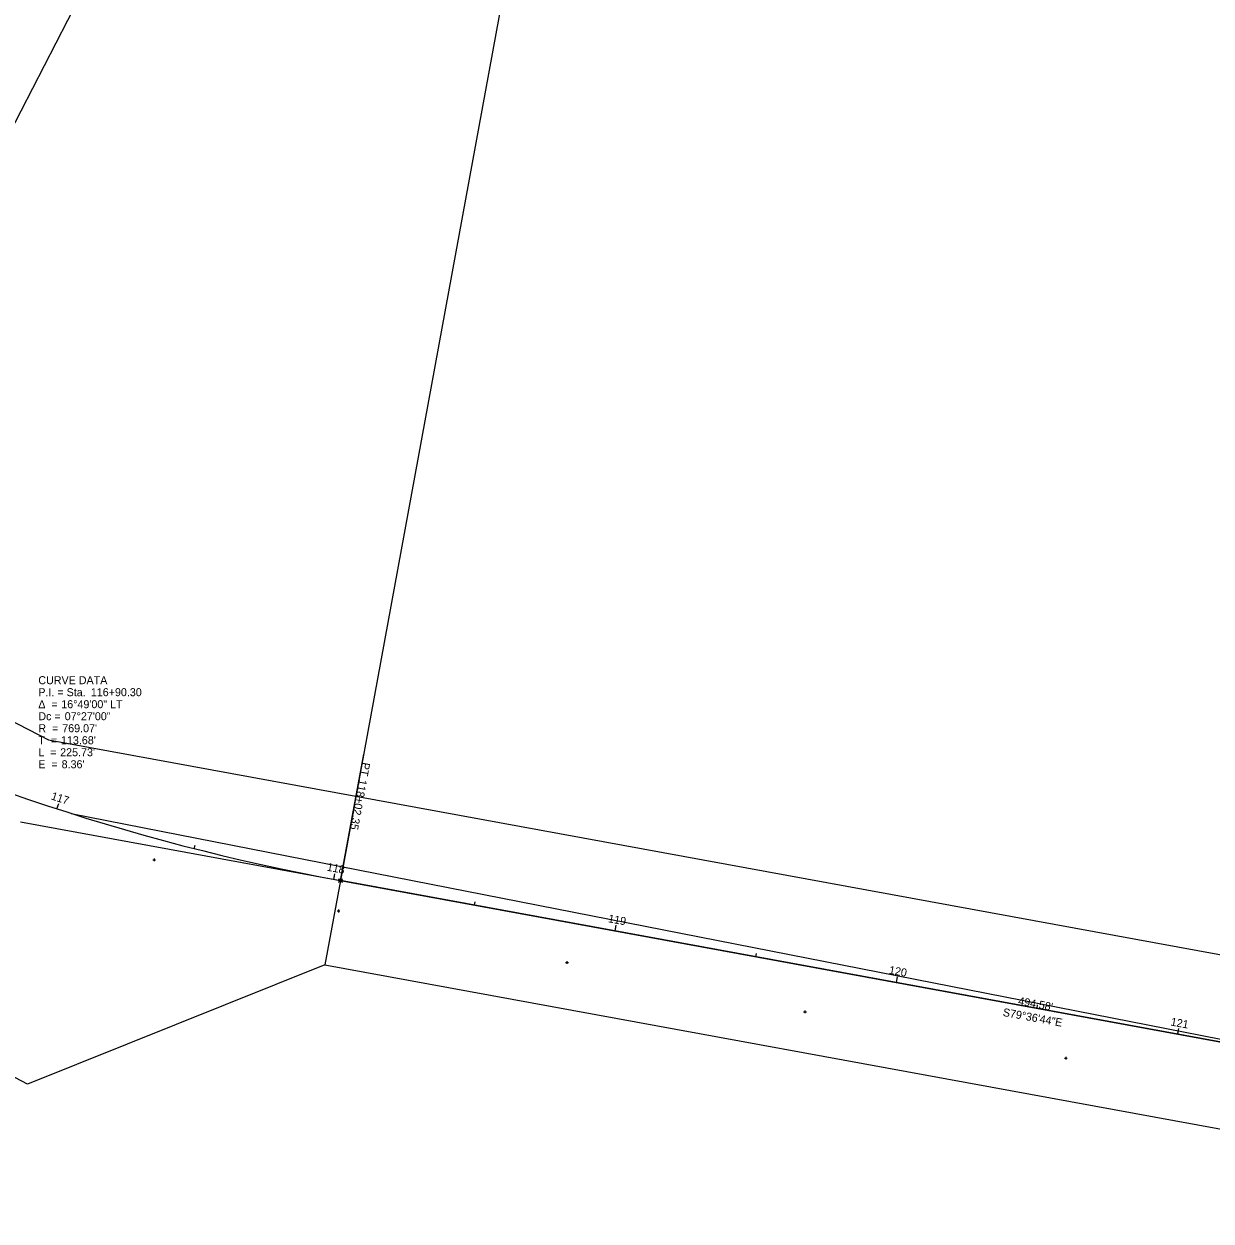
# Model space of a CAD drawing. Extents: x 2003596 to 2006888, y 571866 to 574416.
# Drawn here: x 2004434.3 to 2004849.5, y 572605.4 to 573024.1 of the extents above; entities that cross this region are included whole.
import ezdxf

# ---------------------------------------------------------------- set-up
doc = ezdxf.new("R2010")
doc.units = 0
for name, color, linetype in [('GE_X_Alignment', 7, 'Continuous'), ('GE_X_Alignment_1000_Bearings', 7, 'Continuous'), ('GE_X_Alignment_1000_Cardinal_Points', 7, 'Continuous'), ('GE_X_Alignment_1000_Curve_Data', 7, 'Continuous'), ('GE_X_Alignment_1000_Distances', 7, 'Continuous'), ('GE_X_Alignment_1000_Stations', 7, 'Continuous'), ('GE_X_Alignment_100_Bearings', 7, 'Continuous'), ('GE_X_Alignment_100_Cardinal_Points', 7, 'Continuous'), ('GE_X_Alignment_100_Distances', 7, 'Continuous'), ('GE_X_Alignment_100_Stations', 7, 'Continuous'), ('GE_X_Alignment_500_Bearings', 7, 'Continuous'), ('GE_X_Alignment_500_Cardinal_Points', 7, 'Continuous'), ('GE_X_Alignment_500_Distances', 7, 'Continuous'), ('GE_X_Alignment_500_Stations', 7, 'Continuous'), ('RW_X_CL', 7, 'Continuous'), ('RW_X_Esmt_SH', 7, 'Continuous'), ('SC_Scratch1', 7, 'Continuous'), ('SC_Scratch8', 7, 'Continuous'), ('SV_X_Random_Point', 7, 'Continuous'), ('SV_X_Shot_Marker', 7, 'Continuous')]:
    doc.layers.add(name, color=color, linetype=linetype)

msp = doc.modelspace()

# ---------------------------------------------------------------- linework, layer by layer
at = {"layer": 'GE_X_Alignment'}
msp.add_line((2004545, 572724.5), (2005031.48, 572635.32), dxfattribs=at)
msp.add_arc((2004683.7, 573480.96), 769.07, 242.79359, 259.61026, dxfattribs=at)
at = {"layer": 'GE_X_Alignment_1000_Cardinal_Points'}
msp.add_line((2004545, 572724.5), (2004553.12, 572768.76), dxfattribs=at)
msp.add_circle((2004545, 572724.5), 0.6, dxfattribs=at)
at = {"layer": 'GE_X_Alignment_1000_Stations'}
msp.add_line((2004739.42, 572688.86), (2004739.78, 572690.83), dxfattribs=at)
at = {"layer": 'GE_X_Alignment_100_Cardinal_Points'}
msp.add_line((2004545, 572724.5), (2004553.12, 572768.76), dxfattribs=at)
msp.add_circle((2004545, 572724.5), 0.6, dxfattribs=at)
at = {"layer": 'GE_X_Alignment_100_Stations'}
for p, q in [((2004445.86, 572749.59), (2004446.48, 572751.49)), ((2004493.88, 572735.68), (2004494.17, 572736.85)), ((2004542.7, 572724.92), (2004543.06, 572726.89)), ((2004591.88, 572715.91), (2004592.09, 572717.09)), ((2004641.06, 572706.89), (2004641.42, 572708.86)), ((2004690.24, 572697.87), (2004690.45, 572699.05)), ((2004739.42, 572688.86), (2004739.78, 572690.83)), ((2004788.6, 572679.84), (2004788.81, 572681.02)), ((2004837.78, 572670.83), (2004838.14, 572672.79))]:
    msp.add_line(p, q, dxfattribs=at)
at = {"layer": 'GE_X_Alignment_500_Cardinal_Points'}
msp.add_line((2004545, 572724.5), (2004553.12, 572768.76), dxfattribs=at)
msp.add_circle((2004545, 572724.5), 0.6, dxfattribs=at)
at = {"layer": 'GE_X_Alignment_500_Stations'}
for p, q in [((2004445.86, 572749.59), (2004446.23, 572750.73)), ((2004542.7, 572724.92), (2004542.92, 572726.1)), ((2004641.06, 572706.89), (2004641.27, 572708.07)), ((2004739.42, 572688.86), (2004739.78, 572690.83)), ((2004837.78, 572670.83), (2004837.99, 572672.01))]:
    msp.add_line(p, q, dxfattribs=at)
at = {"layer": 'RW_X_CL'}
msp.add_line((2005031.48, 572635.32), (2004545, 572724.5), dxfattribs=at)
at = {"layer": 'RW_X_Esmt_SH'}
for p, q in [((2004345.8, 572823.66), (2004442.88, 572773.75)), ((2004442.88, 572773.75), (2004550.42, 572754.03)), ((2004550.41, 572754.01), (2005034.78, 572665.22)), ((2004435.53, 572653.29), (2004295.51, 572725.82)), ((2004539.59, 572694.99), (2004435.53, 572653.29)), ((2004539.59, 572694.99), (2005028.18, 572605.42))]:
    msp.add_line(p, q, dxfattribs=at)
at = {"layer": 'SC_Scratch1'}
for p, q in [((2004683.7, 573480.96), (2004332.08, 572796.97)), ((2004683.7, 573480.96), (2004545, 572724.5)), ((2004433.11, 572745.04), (2005031.48, 572635.32)), ((2004545, 572724.5), (2004539.59, 572694.99))]:
    msp.add_line(p, q, dxfattribs=at)
at = {"layer": 'SC_Scratch8'}
msp.add_line((2005021.66, 572635.7), (2004450.87, 572747.83), dxfattribs=at)
at = {"layer": 'SV_X_Random_Point'}
for p, q in [((2004544.34, 572723.83), (2004545.67, 572725.17)), ((2004544.34, 572725.17), (2004545.67, 572723.83))]:
    msp.add_line(p, q, dxfattribs=at)
at = {"layer": 'SV_X_Shot_Marker'}
for p, q in [((2004479.34, 572731.78), (2004480.34, 572731.78)), ((2004479.84, 572732.28), (2004479.84, 572731.28)), ((2004479.84, 572731.78), (2004479.84, 572731.78)), ((2004543.81, 572713.89), (2004544.81, 572713.89)), ((2004544.31, 572714.39), (2004544.31, 572713.39)), ((2004544.31, 572713.89), (2004544.31, 572713.89)), ((2004623.72, 572695.87), (2004624.72, 572695.87)), ((2004624.22, 572696.37), (2004624.22, 572695.37)), ((2004624.22, 572695.87), (2004624.22, 572695.87)), ((2004706.95, 572678.62), (2004707.95, 572678.62)), ((2004707.45, 572679.12), (2004707.45, 572678.12)), ((2004707.45, 572678.62), (2004707.45, 572678.62)), ((2004798.19, 572662.37), (2004799.19, 572662.37)), ((2004798.69, 572662.87), (2004798.69, 572661.87)), ((2004798.69, 572662.37), (2004798.69, 572662.37))]:
    msp.add_line(p, q, dxfattribs=at)

# ---------------------------------------------------------------- texts
at = {"layer": 'GE_X_Alignment_1000_Bearings'}
msp.add_text('S79°36\'44"E', height=2.8, rotation=349.6122, dxfattribs=at).set_placement((2004776.48, 572677.18))
at = {"layer": 'GE_X_Alignment_1000_Cardinal_Points'}
for s, p in [('PT', (2004552.66, 572766.02)), ('118+02.35', (2004551.57, 572760.04))]:
    msp.add_text(s, height=2.8, rotation=259.6122, dxfattribs=at).set_placement(p)
at = {"layer": 'GE_X_Alignment_1000_Curve_Data'}
for s, p in [('CURVE DATA', (2004439.35, 572793.19)), ('P.I. = Sta. ', (2004439.35, 572788.99)), ('116+90.30', (2004457.71, 572788.99)), ('Δ  = ', (2004439.35, 572784.79)), ('16°49\'00" LT', (2004447.37, 572784.79)), ('Dc = ', (2004439.35, 572780.59)), ('07°27\'00"', (2004448.58, 572780.59)), ('R  = ', (2004439.35, 572776.39)), ("769.07'", (2004447.71, 572776.39)), ('T  = ', (2004439.35, 572772.19)), ("113.68'", (2004447.28, 572772.19)), ('L  = ', (2004439.35, 572767.99)), ("225.73'", (2004446.99, 572767.99)), ('E  = ', (2004439.35, 572763.79)), ("8.36'", (2004447.5, 572763.79))]:
    msp.add_text(s, height=2.8, dxfattribs=at).set_placement(p)
at = {"layer": 'GE_X_Alignment_1000_Distances'}
msp.add_text("494.58'", height=2.8, rotation=349.6122, dxfattribs=at).set_placement((2004781.87, 572681.12))
at = {"layer": 'GE_X_Alignment_1000_Stations'}
msp.add_text('120', height=2.8, rotation=349.6122, dxfattribs=at).set_placement((2004736.65, 572691.96))
at = {"layer": 'GE_X_Alignment_100_Bearings'}
msp.add_text('S79°36\'44"E', height=2.8, rotation=349.6122, dxfattribs=at).set_placement((2004776.48, 572677.18))
at = {"layer": 'GE_X_Alignment_100_Cardinal_Points'}
for s, p in [('PT', (2004552.66, 572766.02)), ('118+02.35', (2004551.57, 572760.04))]:
    msp.add_text(s, height=2.8, rotation=259.6122, dxfattribs=at).set_placement(p)
at = {"layer": 'GE_X_Alignment_100_Distances'}
msp.add_text("494.58'", height=2.8, rotation=349.6122, dxfattribs=at).set_placement((2004781.87, 572681.12))
at = {"layer": 'GE_X_Alignment_100_Stations'}
for s, rotation, p in [('117', 341.9854, (2004443.59, 572752.95)), ('118', 349.4354, (2004540.08, 572728)), ('119', 349.6122, (2004638.46, 572709.96)), ('120', 349.6122, (2004736.65, 572691.96)), ('121', 349.6122, (2004835.17, 572673.85))]:
    msp.add_text(s, height=2.8, rotation=rotation, dxfattribs=at).set_placement(p)
at = {"layer": 'GE_X_Alignment_500_Bearings'}
msp.add_text('S79°36\'44"E', height=2.8, rotation=349.6122, dxfattribs=at).set_placement((2004776.48, 572677.18))
at = {"layer": 'GE_X_Alignment_500_Cardinal_Points'}
for s, p in [('PT', (2004552.66, 572766.02)), ('118+02.35', (2004551.57, 572760.04))]:
    msp.add_text(s, height=2.8, rotation=259.6122, dxfattribs=at).set_placement(p)
at = {"layer": 'GE_X_Alignment_500_Distances'}
msp.add_text("494.58'", height=2.8, rotation=349.6122, dxfattribs=at).set_placement((2004781.87, 572681.12))
at = {"layer": 'GE_X_Alignment_500_Stations'}
msp.add_text('120', height=2.8, rotation=349.6122, dxfattribs=at).set_placement((2004736.65, 572691.96))

doc.saveas('drawing.dxf')
